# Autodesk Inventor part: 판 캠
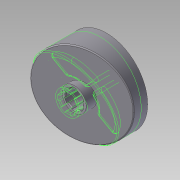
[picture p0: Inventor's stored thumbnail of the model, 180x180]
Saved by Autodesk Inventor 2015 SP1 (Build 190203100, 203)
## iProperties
Company: 한국ATC센터
Created: 2014-07
Part Number: 판 캠
Document SubType Name: 모델링
Designer: KYOUNG IL JANG
Material: 강철
Appearance: 알루미늄 - 평지
Mass: 681.587 g
Surface Area: 331.303 cm^2
Volume: 86.8264 cm^3
Density: 7.85 g/cm^3
변환 표준: STEP AP214IS
파일 이름: C:\Users\SeoGD\Desktop\?쒗뿕\??stp
전처리기: Build: 253, Release: 2010 SP1 - Date: Wed 07/29/2009
전송 단위: 밀리미터
불확실성: 0.01
Author: KYOUNG IL JANG
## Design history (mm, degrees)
node "작업 평면4"
sketch "스케치1"
  geometry: C1 r 44.5 at (0, 0); 1 further point
  constraints: 1 centre point, 1 coincident
  dimensions: "d25" = 89 diameter of C1
extrude "돌출1" new body sketch "스케치1" distance "d1" = 40; taper "d2" = 0 deg
sketch "스케치2"
  geometry: L1 (-44.5, 15)-(44.5, 38.847); L2 (-44.5, 0)-(-44.5, 40) reference; L3 (-44.5, 40)-(44.5, 40) reference; L4 (44.5, 0)-(44.5, 40) reference; 1 further point
  constraints: 2 end point, 2 point on line
  dimensions: "d26" = 15 distance of L2.start L1.start; "d27" = 75 deg angle of L1 L2
extrude "돌출2" cut sketch "스케치2" stored distance "d5" = 40; taper "d6" = 0 deg
node "작업 평면1"
sketch "스케치3"
  geometry: C1 r 13 at (0, 0); 1 further point
  constraints: 1 centre point, 1 coincident
  dimensions: "d9" = 26 diameter of C1
extrude "돌출3" join sketch "스케치3" distance "d10" = 38; taper "d11" = 0 deg
hole "구멍1" diameter "d14" = 18; stored, may be unused: countersink angle "d18" = 90 deg, drill point angle "d20" = 118 deg; dims "d12" = 10, "d13" = 10, "d15" = 6, "d16" = 4, "d17" = 2, "d19" = 8
feature "쉘2" dims "d29" = 5
sketch "스케치6"
  geometry: C1 r 17.5 at (0, 0); C2 r 14 at (0, 0) reference; 1 further point
  constraints: 1 centre point, 1 coincident
  dimensions: "d28" = 35 diameter of C1
extrude "돌출4" join sketch "스케치6" stored distance "d30" = 38; taper "d31" = 0 deg
fillet "모깎기1" dims "d32" = 3
chamfer "모따기1" distance "d21" = 1; stored, may be unused: second distance "d22" = 2, angle "d23" = 45 deg
sketch "스케치7"
  geometry: L1 (-12.374, 12.374)-(-27.931, 27.931); A1 r 39.5 centre (0, 0) between (-27.931, 27.931) and (0, 39.5) reference; 2 further points
  constraints: 2 end point, 2 point on circle, 1 point on line, 1 vertical alignment, 2 other
  dimensions: "d33" = 45 deg dimension on point (0, 0) L1.start A1.end
feature "리브1" sketch "스케치7" dims "d34" = 5, "d35" = 1, "d36" = 0
fillet "모깎기2" dims "d37" = 3
sketch "스케치8"
  geometry: L1 (2.5, 10.712)-(2.5, 8.646); L2 (-2.5, 10.712)-(-2.5, 8.646); A1 r 11 centre (0, 0) between (2.5, 10.712) and (-2.5, 10.712); A2 r 9 centre (0, 0) between (2.5, 8.646) and (-2.5, 8.646) reference; 1 further point
  constraints: 4 end point, 4 point on circle, 2 parallel, 1 centre point, 1 coincident, 1 vertical
  dimensions: "d41" = 22 diameter of A1; "d42" = 5 distance between parallel lines of L1 L2
extrude "돌출5" cut sketch "스케치8" stored distance "d43" = 38; taper "d44" = 0 deg
fillet "모깎기3" dims "d48" = 1
node "솔리드1"
node "솔리드 본체"
node "곡면 본체"
pattern_circular "원형 패턴1" dims angle "d39" = 360 deg
pattern_circular "원형 패턴2" dims angle "d46" = 360 deg
node "솔리드2"
